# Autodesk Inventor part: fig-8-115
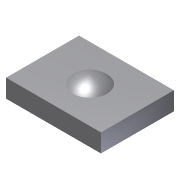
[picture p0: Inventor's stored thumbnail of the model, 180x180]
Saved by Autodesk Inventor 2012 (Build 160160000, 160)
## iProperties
Created: 2009-09
Part Number: fig-8-115
Document SubType Name: Modeling
Designer: Sham
Density: 1 g/cm^3
Material: Default
Author: Sham
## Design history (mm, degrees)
sketch "Sketch1"
  geometry: L1 (-26, 20)-(0, 20); L2 (0, 20)-(0, 0); L3 (0, 0)-(-26, 0); L4 (-26, 0)-(-26, 20)
  constraints: 8 end point, 2 parallel, 1 horizontal, 1 perpendicular
extrude "Extrusion1" new body sketch "Sketch1" distance "d0" = 5; taper "d1" = 0 deg
workplane "Work Plane1"
feature "Sculpt2"
body "Solid1"
sketch "Sketch2"
  geometry: L1 (13, 8)-(13, 5); A1 r 7.517 centre (12.377, -0.349) between (17.658, 5) and (13, 7.142)
  constraints: 2 end point, 2 point on circle, 1 centre point
body "Srf2"
feature "RevolutionSrf2" dims angle "d4" = 90 deg
